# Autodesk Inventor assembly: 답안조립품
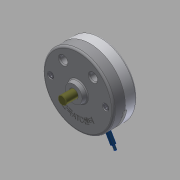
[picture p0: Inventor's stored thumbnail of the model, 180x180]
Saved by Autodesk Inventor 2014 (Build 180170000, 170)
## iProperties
Created: 2015-06
Part Number: 답안조립품
Document SubType Name: Assembly
Designer: MYHOME
Author: MYHOME
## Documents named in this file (10)
- C:\Documents and Settings\MYHOME\바탕 화면\450631V1040\답안조립품.iam
- C:\Documents and Settings\MYHOME\바탕 화면\450631V1040\본체.ipt
- C:\Documents and Settings\MYHOME\바탕 화면\450631V1040\덮개.ipt
- C:\Documents and Settings\MYHOME\바탕 화면\450631V1040\베어링62_22.ipt
- C:\Documents and Settings\MYHOME\바탕 화면\450631V1040\축.ipt
- C:\Documents and Settings\MYHOME\바탕 화면\450631V1040\멈춤링.ipt
- C:\Documents and Settings\MYHOME\바탕 화면\450631V1040\M10x35.ipt
- C:\Documents and Settings\MYHOME\바탕 화면\450631V1040\슬라이더2.ipt
- C:\Documents and Settings\MYHOME\바탕 화면\450631V1040\슬라이더.ipt
- C:\Documents and Settings\MYHOME\바탕 화면\450631V1040\평행핀.ipt
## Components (7 placed, 4 different names)
1. KS B 2023 62/22 - 22 x 50 x 14:1 — 각도:1
2. KS B 2023 62/22 - 22 x 50 x 14:2 — 각도:2
3. KS B 1336 22 x 1.2:1 — 각도:3
4. KS B 1336 22 x 1.2:2 — 각도:4
5. KS B 1003 - 미터 M 10 x 35:1
6. KS B 1003 - 미터 M 10 x 35:2
7. KS B 1320 B B 5 x  20:1
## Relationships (4: Angle 4)
- 각도:1 [Angle]: KS B 2023 62/22 - 22 x 50 x 14:1
- 각도:2 [Angle]: KS B 2023 62/22 - 22 x 50 x 14:2
- 각도:3 [Angle]: KS B 1336 22 x 1.2:1
- 각도:4 [Angle]: KS B 1336 22 x 1.2:2
